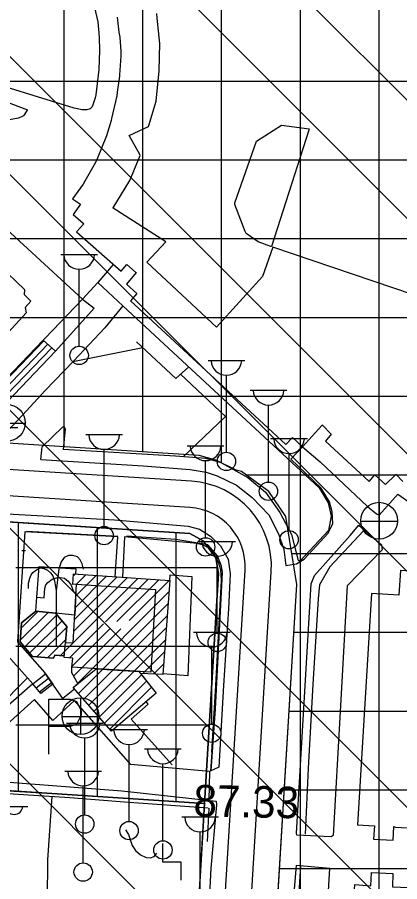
# Model space of a CAD drawing. Extents: x 417995 to 421451, y 4454518 to 4458015.
# Drawn here: x 420586.8 to 420659.6, y 4456253.5 to 4456418.1 of the extents above; entities that cross this region are included whole.
import ezdxf

# ---------------------------------------------------------------- set-up
doc = ezdxf.new("R2010")
doc.units = 0
for name, color, linetype in [('ADAKENARI', 7, 'Continuous'), ('B_Betonzemin', 7, 'Continuous'), ('B_Imalat', 7, 'Continuous'), ('B_Kapi', 7, 'Continuous'), ('B_Merdiven', 7, 'Continuous'), ('B_Resmi', 7, 'Continuous'), ('B_Tarama', 7, 'Continuous'), ('B_Teras', 7, 'Continuous'), ('Hid_Havuz', 7, 'Continuous'), ('KALDIRIM_FAT', 7, 'Continuous'), ('O_Park_Bahce', 7, 'Continuous'), ('PL_KAMU_HİZMET_ALANI', 7, 'Continuous'), ('PL_TİCARET', 7, 'Continuous'), ('S_Cad_Sok_Lambasi', 7, 'Continuous'), ('S_Cesme', 7, 'Continuous'), ('S_Elektrik_Diregi', 7, 'Continuous'), ('S_Otopark', 7, 'Continuous'), ('S_Rogar_Kapagi', 7, 'Continuous'), ('S_Tek_Agac', 7, 'Continuous'), ('Sinir_Duvar_tek_tarafa_ait', 7, 'Continuous'), ('Sinir_Ist_Duvari', 7, 'Continuous'), ('Sinir_Parmaklik_bir_taraf', 7, 'Continuous'), ('Sinir_Tel_bir_taraf', 7, 'Continuous'), ('SN_TR_SIVILASMA', 7, 'Continuous'), ('TRFAT_KHA', 7, 'Continuous'), ('TRFAT_TİCARET', 7, 'Continuous'), ('Y_Yol_Kotu', 7, 'Continuous'), ('Yol_Kaldirim_kenari_bordurtasi', 7, 'Continuous'), ('Yol_Sose', 7, 'Continuous')]:
    doc.layers.add(name, color=color, linetype=linetype)

msp = doc.modelspace()

# ---------------------------------------------------------------- linework, layer by layer
at = {"layer": 'ADAKENARI'}
for p, q in [((420621.4, 4456334.69), (420462.71, 4456344.9)), ((420624.59, 4456333.76), (420621.4, 4456334.69)), ((420628.47, 4456331.87), (420624.59, 4456333.76)), ((420629.47, 4456331.61), (420628.47, 4456331.87)), ((420634.68, 4456327.8), (420629.47, 4456331.61)), ((420637.88, 4456323.02), (420634.68, 4456327.8)), ((420619.6, 4456319.78), (420515.36, 4456326.47)), ((420640, 4456310.1), (420637.88, 4456323.02)), ((420622.14, 4456318.43), (420619.6, 4456319.78)), ((420624.55, 4456315.15), (420622.14, 4456318.43)), ((420625.1, 4456312.17), (420624.55, 4456315.15)), ((420622.45, 4456268.35), (420625.1, 4456312.17)), ((420623.45, 4456037.14), (420640, 4456310.1)), ((420538.18, 4456273.87), (420592.42, 4456270.32)), ((420592.42, 4456270.32), (420622.45, 4456268.35)), ((420618.91, 4456209.8), (420622.45, 4456268.35))]:
    msp.add_line(p, q, dxfattribs=at)
at = {"layer": 'B_Betonzemin'}
for points in [[(420610.68, 4456355.21), (420597.38, 4456352.53)], [(420617.84, 4456350.14), (420626.39, 4456342.11), (420618.35, 4456334.43)]]:
    msp.add_lwpolyline(points, dxfattribs=at)
at = {"layer": 'B_Imalat'}
msp.add_lwpolyline([(420605.8, 4456418.18), (420606.1, 4456415.32), (420606.3, 4456414.36), (420606.52, 4456411.66), (420606.49, 4456410.76), (420606.22, 4456407.17), (420606.21, 4456406.93), (420605.8, 4456403.88), (420605.76, 4456403.16), (420604.74, 4456398.89), (420604.62, 4456398.51), (420603.78, 4456395.54), (420601.98, 4456391.18), (420601.69, 4456390.51), (420599.63, 4456386.95), (420599.32, 4456386.36), (420597.3, 4456383.54), (420598.82, 4456382.57), (420597.4, 4456380.59), (420599.35, 4456378.92), (420599.45, 4456378.83), (420598.06, 4456377.29), (420606.53, 4456369.76), (420607.66, 4456371.06), (420609.29, 4456369.62), (420609.38, 4456369.5), (420607.58, 4456367.32), (420609.54, 4456365.56), (420608.33, 4456364.14), (420637.91, 4456336.78), (420639.15, 4456338.13), (420641.07, 4456336.31), (420644.75, 4456340.39), (420644.81, 4456340.5), (420646.54, 4456338.71), (420645.48, 4456337.39), (420653.75, 4456329.71), (420654.87, 4456330.97), (420656.89, 4456329.14), (420658.8, 4456330.99), (420658.86, 4456331.1), (420660.2, 4456329.74)], dxfattribs=at)
msp.add_lwpolyline([(420580.63, 4456381.48), (420580.52, 4456381.22), (420563.48, 4456362.98), (420563.56, 4456362.98), (420581.88, 4456346.4), (420582.07, 4456346.6), (420599.18, 4456364.48), (420599.18, 4456364.48)], close=True, dxfattribs=at)
at = {"layer": 'B_Kapi'}
for points in [[(420599.18, 4456364.48), (420602.14, 4456367.62)], [(420623.35, 4456274.46), (420623.24, 4456269)]]:
    msp.add_lwpolyline(points, dxfattribs=at)
at = {"layer": 'B_Merdiven'}
for p, q in [((420582, 4456346.3), (420591.84, 4456356.52)), ((420582.76, 4456345.65), (420592.58, 4456355.86)), ((420581.42, 4456342.8), (420593.33, 4456355.2)), ((420589.73, 4456291.18), (420592.14, 4456293.06)), ((420590.37, 4456290.41), (420592.72, 4456292.25)), ((420591.01, 4456289.65), (420593.3, 4456291.43))]:
    msp.add_line(p, q, dxfattribs=at)
for points in [[(420594.08, 4456354.53), (420582.17, 4456342.14), (420569.36, 4456353.39), (420570.68, 4456354.83), (420581.96, 4456344.63), (420582.92, 4456345.52), (420581.88, 4456346.4), (420591.69, 4456356.65)], [(420589.73, 4456291.18), (420592.14, 4456293.06), (420593.54, 4456291.08), (420591.25, 4456289.36)]]:
    msp.add_lwpolyline(points, close=True, dxfattribs=at)
at = {"layer": 'B_Resmi'}
for points in [[(420598.03, 4456310.17), (420597.36, 4456310.1), (420597.49, 4456312.13), (420615.79, 4456310.83), (420614.5, 4456292.96), (420610.24, 4456293.13), (420613.24, 4456289.41), (420604.73, 4456282.16), (420597.4, 4456290.48), (420598.33, 4456291.23), (420597.13, 4456293.29), (420597.15, 4456294.33), (420597.33, 4456296.08), (420595.7, 4456296.2), (420595.73, 4456296.52), (420593.94, 4456296.61), (420593.68, 4456296.07), (420589.64, 4456296.35), (420587.33, 4456299.17), (420587.59, 4456302.8), (420590.3, 4456304.99), (420594.02, 4456304.62), (420596.22, 4456302.12), (420595.94, 4456299.07), (420597.41, 4456298.96)], [(420579.71, 4456302.37), (420589.73, 4456291.18), (420578.05, 4456280.97), (420556.86, 4456282.24)]]:
    msp.add_lwpolyline(points, close=True, dxfattribs=at)
at = {"layer": 'B_Tarama'}
for p, q in [((420595.03, 4456296.55), (420609.74, 4456311.26)), ((420597.47, 4456311.72), (420597.85, 4456312.1)), ((420597.53, 4456301.18), (420607.76, 4456311.4)), ((420597.66, 4456303.42), (420605.78, 4456311.54)), ((420597.78, 4456305.67), (420603.79, 4456311.68)), ((420597.91, 4456307.92), (420601.81, 4456311.82)), ((420598.03, 4456310.17), (420599.83, 4456311.96)), ((420603.58, 4456302.99), (420611.72, 4456311.12)), ((420605.74, 4456303.02), (420613.7, 4456310.98)), ((420608.06, 4456303.22), (420615.68, 4456310.84)), ((420598.28, 4456291.32), (420615.63, 4456308.67)), ((420598.41, 4456289.33), (420615.47, 4456306.39)), ((420587.35, 4456299.48), (420592.63, 4456304.76)), ((420587.52, 4456301.77), (420590.7, 4456304.95)), ((420588.15, 4456298.16), (420594.3, 4456304.31)), ((420589.11, 4456297), (420595.29, 4456303.18)), ((420599.41, 4456288.2), (420615.3, 4456304.1)), ((420590.52, 4456296.29), (420596.2, 4456301.97)), ((420596.72, 4456296.13), (420603.16, 4456302.57)), ((420597.17, 4456294.45), (420604.37, 4456301.66)), ((420597.5, 4456292.66), (420606.52, 4456301.68)), ((420600.4, 4456287.08), (420615.14, 4456301.81)), ((420592.5, 4456296.15), (420596, 4456299.64)), ((420601.39, 4456285.95), (420614.97, 4456299.53)), ((420610.68, 4456293.12), (420614.81, 4456297.24)), ((420612.72, 4456293.03), (420614.65, 4456294.96)), ((420577.44, 4456281.01), (420588.73, 4456292.3)), ((420602.39, 4456284.82), (420610.45, 4456292.88)), ((420603.38, 4456283.69), (420611.39, 4456291.7)), ((420597.42, 4456290.46), (420597.6, 4456290.64)), ((420604.38, 4456282.56), (420612.34, 4456290.53))]:
    msp.add_line(p, q, dxfattribs=at)
at = {"layer": 'B_Teras'}
msp.add_lwpolyline([(420665.95, 4456364.03), (420635.46, 4456374.37), (420633.49, 4456368.74), (420624.73, 4456359.14), (420611.47, 4456371.5), (420615.08, 4456375.4), (420605.01, 4456381.79), (420605.01, 4456381.83), (420608.22, 4456387.04), (420608.22, 4456387.04), (420610.18, 4456391.85), (420610.11, 4456391.98), (420608.09, 4456395.62), (420611.79, 4456397.35), (420611.82, 4456397.56), (420613.23, 4456402.15), (420613.79, 4456407.94), (420613.94, 4456413.17), (420613.43, 4456417.99), (420613.33, 4456418.89)], dxfattribs=at)
for points in [[(420642.35, 4456396.87), (420642.29, 4456396.66), (420635.21, 4456374.47), (420635.04, 4456374.51), (420632.65, 4456375.38), (420630.36, 4456376.97), (420630.18, 4456377.35), (420628.22, 4456382.48), (420628.22, 4456382.8), (420632.32, 4456394.57), (420632.32, 4456394.57), (420637.06, 4456397.59)], [(420583.32, 4456370.88), (420583.32, 4456370.88), (420588.16, 4456366.28), (420588.09, 4456365.35), (420589.37, 4456364.1), (420588.27, 4456362.89), (420588.46, 4456361.84), (420583.75, 4456356.68), (420583.16, 4456357.24), (420581.64, 4456355.62), (420580.35, 4456356.89), (420579.23, 4456356.65), (420574.39, 4456361.79), (420574.45, 4456362.24), (420573.28, 4456363.64), (420574.32, 4456364.7), (420574.17, 4456365.79), (420574.21, 4456365.81), (420578.88, 4456370.67), (420579.77, 4456370.76), (420581.08, 4456371.96), (420582.32, 4456370.82)], [(420598.03, 4456310.17), (420613.1, 4456309.13), (420612.2, 4456293.41), (420597.15, 4456294.33), (420597.33, 4456296.08), (420595.7, 4456296.2), (420595.94, 4456299.07), (420597.41, 4456298.96)], [(420595.94, 4456299.07), (420596.22, 4456302.12), (420594.02, 4456304.62), (420590.3, 4456304.99), (420587.59, 4456302.8), (420587.33, 4456299.17), (420589.64, 4456296.35), (420593.68, 4456296.07), (420593.94, 4456296.61), (420595.73, 4456296.52)], [(420609.91, 4456293.55), (420613.24, 4456289.41), (420604.73, 4456282.16), (420597.4, 4456290.48), (420601.8, 4456294.05)]]:
    msp.add_lwpolyline(points, close=True, dxfattribs=at)
at = {"layer": 'Hid_Havuz'}
for points in [[(420599.4, 4456312.99), (420599.16, 4456314.04), (420598.77, 4456314.81), (420598.21, 4456315.37), (420597.34, 4456315.62), (420596.5, 4456315.62), (420595.69, 4456315.23), (420595.13, 4456314.39), (420594.68, 4456313.06), (420594.15, 4456308.86)], [(420588.9, 4456309.35), (420588.94, 4456310.37), (420589.15, 4456311.31), (420589.43, 4456311.91), (420589.74, 4456312.36), (420590.41, 4456312.92), (420591.11, 4456313.24), (420591.84, 4456313.13), (420592.54, 4456312.82), (420593.1, 4456312.29), (420593.56, 4456311.73), (420593.84, 4456310.82), (420593.98, 4456310.02), (420594.15, 4456308.86), (420594.15, 4456298.36)]]:
    msp.add_lwpolyline(points, dxfattribs=at)
msp.add_lwpolyline([(420590.49, 4456307.69), (420591.87, 4456307.53), (420591.95, 4456308.42), (420592.02, 4456309.42), (420592.23, 4456310.01), (420592.59, 4456310.45), (420593.42, 4456311.09), (420594.26, 4456311.38), (420595.05, 4456311.45), (420595.77, 4456311.29), (420596.45, 4456310.76), (420597.03, 4456309.94), (420597.46, 4456308.68), (420597.95, 4456308.63), (420597.71, 4456304.27), (420594.02, 4456304.62), (420590.3, 4456304.99)], close=True, dxfattribs=at)
at = {"layer": 'KALDIRIM_FAT'}
for p, q in [((420619.92, 4456329.77), (420400.07, 4456343.92)), ((420619.6, 4456324.78), (420399.21, 4456338.96)), ((420613.57, 4456039.35), (420630.15, 4456312.83)), ((420618.56, 4456039.04), (420635.14, 4456312.53))]:
    msp.add_line(p, q, dxfattribs=at)
for radius in [16.29, 11.29]:
    msp.add_arc((420618.88, 4456313.52), radius, 356.5303, 86.3195, dxfattribs=at)
at = {"layer": 'O_Park_Bahce'}
for points in [[(420601.46, 4456420), (420602.08, 4456417.26), (420602.34, 4456414.38), (420602.43, 4456411.82), (420602.3, 4456408.22), (420601.75, 4456403.35), (420601.6, 4456402.82), (420601.03, 4456401.1), (420600.67, 4456400.69), (420599.99, 4456400.49), (420599.13, 4456400.55), (420597.61, 4456400.85), (420585.47, 4456404.58), (420584.56, 4456404.98), (420584.42, 4456405.04), (420574.57, 4456408.13), (420574.21, 4456408.38), (420574.2, 4456409.57), (420574.22, 4456409.7), (420574.15, 4456412.22), (420574, 4456413.58), (420573.93, 4456413.73), (420573.94, 4456414.21), (420574.07, 4456414.55)], [(420580.13, 4456403.74), (420588.69, 4456400.49), (420588.65, 4456400.43), (420587.93, 4456399.4), (420587.84, 4456399.29), (420587.02, 4456398.91), (420579.59, 4456397.6)], [(420599.18, 4456364.48), (420601.4, 4456362.71), (420594.08, 4456354.53)]]:
    msp.add_lwpolyline(points, dxfattribs=at)
at = {"layer": 'PL_KAMU_HİZMET_ALANI'}
msp.add_lwpolyline([(420383.86, 4456251.47), (420387.5, 4456254.04), (420390.9, 4456256.93), (420394.02, 4456260.12), (420396.85, 4456263.57), (420399.35, 4456267.26), (420401.52, 4456271.16), (420403.32, 4456275.23), (420404.75, 4456279.46), (420405.48, 4456281.76), (420405.76, 4456282.54), (420460.36, 4456278.96), (420512.02, 4456275.58), (420538.18, 4456273.87), (420592.42, 4456270.32), (420622.45, 4456268.35), (420618.91, 4456209.8)], dxfattribs=at)
at = {"layer": 'PL_TİCARET'}
msp.add_lwpolyline([(420623.45, 4456037.14), (420640, 4456310.1), (420637.88, 4456323.02), (420634.68, 4456327.8), (420629.47, 4456331.61), (420628.47, 4456331.87), (420624.59, 4456333.76), (420621.4, 4456334.69), (420462.71, 4456344.9), (420462.86, 4456348.74), (420454.39, 4456348.66), (420437.97, 4456349.54), (420422.37, 4456351.96), (420413.66, 4456354.19), (420405.54, 4456357.63), (420398.67, 4456362.62), (420394.62, 4456367.08), (420390.97, 4456372.75), (420388.74, 4456379.85), (420385.69, 4456393.42), (420394.63, 4456520.03)], dxfattribs=at)
msp.add_lwpolyline([(420515.36, 4456326.47), (420619.6, 4456319.78), (420622.14, 4456318.43), (420624.55, 4456315.15), (420625.1, 4456312.17), (420622.45, 4456268.35), (420592.42, 4456270.32), (420538.18, 4456273.87), (420512.02, 4456275.58), (420513.34, 4456295.79)], close=True, dxfattribs=at)
at = {"layer": 'S_Cad_Sok_Lambasi'}
for p, q in [((420595.06, 4456372.98), (420602.06, 4456372.98)), ((420598.56, 4456355.48), (420598.56, 4456370.15)), ((420623.09, 4456352.79), (420630.09, 4456352.79)), ((420626.59, 4456335.29), (420626.59, 4456349.97)), ((420631.1, 4456347.11), (420638.1, 4456347.11)), ((420634.6, 4456329.61), (420634.6, 4456344.28)), ((420579.85, 4456340), (420586.85, 4456340)), ((420599.81, 4456338.65), (420606.81, 4456338.65)), ((420635.02, 4456337.88), (420642.02, 4456337.88)), ((420603.31, 4456321.15), (420603.31, 4456335.82)), ((420619.12, 4456336.51), (420626.12, 4456336.51)), ((420638.52, 4456320.38), (420638.52, 4456335.05)), ((420622.62, 4456319.01), (420622.62, 4456333.69)), ((420621.34, 4456318.31), (420628.34, 4456318.31)), ((420624.84, 4456300.81), (420624.84, 4456315.49)), ((420620.3, 4456301), (420627.3, 4456301)), ((420623.8, 4456283.5), (420623.8, 4456298.18)), ((420596.12, 4456283.71), (420603.12, 4456283.71)), ((420604.55, 4456282.45), (420611.55, 4456282.45)), ((420599.62, 4456266.21), (420599.62, 4456280.88)), ((420608.05, 4456264.95), (420608.05, 4456279.62)), ((420611, 4456278.77), (420618, 4456278.77)), ((420614.5, 4456261.27), (420614.5, 4456275.95)), ((420595.82, 4456274.56), (420602.82, 4456274.56)), ((420599.32, 4456257.06), (420599.32, 4456271.73)), ((420618.08, 4456265.81), (420625.08, 4456265.81)), ((420621.58, 4456248.31), (420621.58, 4456262.98))]:
    msp.add_line(p, q, dxfattribs=at)
for centre in [(420598.56, 4456353.73), (420626.59, 4456333.54), (420634.6, 4456327.86), (420603.31, 4456319.4), (420638.52, 4456318.63), (420622.62, 4456317.26), (420624.84, 4456299.06), (420623.8, 4456281.75), (420599.62, 4456264.46), (420608.05, 4456263.2), (420614.5, 4456259.52), (420599.32, 4456255.31)]:
    msp.add_circle(centre, 1.75, dxfattribs=at)
for centre in [(420598.56, 4456373.08), (420626.59, 4456352.89), (420634.6, 4456347.21), (420603.31, 4456338.75), (420638.52, 4456337.98), (420622.62, 4456336.62), (420624.84, 4456318.42), (420623.8, 4456301.11), (420599.62, 4456283.81), (420608.05, 4456282.55), (420614.5, 4456278.88), (420599.32, 4456274.66), (420621.58, 4456265.91)]:
    msp.add_arc(centre, 2.93, 183.298, 356.9072, dxfattribs=at)
at = {"layer": 'S_Cesme'}
msp.add_lwpolyline([(420614.44, 4456260.74), (420614.44, 4456257.24), (420617.94, 4456257.24), (420617.94, 4456253.74)], dxfattribs=at)
at = {"layer": 'S_Elektrik_Diregi'}
msp.add_line((420583.52, 4456267.81), (420588.77, 4456267.81), dxfattribs=at)
msp.add_arc((420586.18, 4456267.96), 1.66, 184.8384, 355.1464, dxfattribs=at)
at = {"layer": 'S_Otopark'}
for points in [[(420592.75, 4456288.25), (420596.85, 4456288.25)], [(420592.75, 4456277.75), (420592.75, 4456288.25)], [(420596.85, 4456288.25), (420598.07, 4456287.83), (420598.91, 4456286.11), (420598.91, 4456285.2), (420598.07, 4456283.42), (420596.85, 4456283.07)], [(420596.85, 4456283.07), (420592.75, 4456283.07)]]:
    msp.add_lwpolyline(points, dxfattribs=at)
at = {"layer": 'S_Rogar_Kapagi'}
for p, q in [((420581.26, 4456340.83), (420588.26, 4456340.83)), ((420655.72, 4456318.72), (420655.72, 4456325.72)), ((420652.15, 4456322.19), (420659.15, 4456322.19)), ((420598.86, 4456281.5), (420598.86, 4456288.5)), ((420595.29, 4456284.96), (420602.29, 4456284.96))]:
    msp.add_line(p, q, dxfattribs=at)
for centre in [(420584.77, 4456340.89), (420655.67, 4456322.25), (420598.8, 4456285.02)]:
    msp.add_circle(centre, 3.5, dxfattribs=at)
at = {"layer": 'S_Tek_Agac'}
msp.add_line((420587.67, 4456316.57), (420588.37, 4456316.57), dxfattribs=at)
at = {"layer": 'Sinir_Duvar_tek_tarafa_ait'}
for points in [[(420593.37, 4456269.68), (420592.54, 4456257.63)], [(420607.21, 4456268.64), (420596.8, 4456269.46)], [(420623.15, 4456267.5), (420607.21, 4456268.64)]]:
    msp.add_lwpolyline(points, dxfattribs=at)
at = {"layer": 'Sinir_Ist_Duvari'}
for points in [[(420605.05, 4456371.07), (420602.14, 4456367.62), (420606.87, 4456363.18)], [(420606.87, 4456363.18), (420603.43, 4456358.97)], [(420606.87, 4456363.18), (420619.06, 4456351.88), (420644.23, 4456328.52), (420645.95, 4456325.66), (420646.51, 4456323.13), (420646.04, 4456320.4), (420640.67, 4456314.67)], [(420619.42, 4456351.55), (420616.96, 4456349.36), (420609.49, 4456356.32)], [(420625.66, 4456333.27), (420622.67, 4456334.1), (420616.9, 4456334.54), (420595.52, 4456335.84)], [(420652.71, 4456320.35), (420646.27, 4456313.47), (420644.31, 4456310.05), (420644.05, 4456307.35), (420643.03, 4456291.07), (420642.15, 4456275.11)], [(420597.69, 4456290.15), (420595.47, 4456288.37), (420592.01, 4456293.24)], [(420616.24, 4456275.71), (420608.46, 4456284.45), (420611.72, 4456287.27), (420611.32, 4456287.78)], [(420596.8, 4456269.46), (420552.59, 4456272.31), (420511.85, 4456275.79)]]:
    msp.add_lwpolyline(points, dxfattribs=at)
at = {"layer": 'Sinir_Parmaklik_bir_taraf'}
for points in [[(420605.93, 4456319.22), (420588.54, 4456320.2)], [(420623.72, 4456274.57), (420624.54, 4456286.43), (420625.83, 4456312.36), (420625.67, 4456313.56), (420624.92, 4456315.53), (420623.05, 4456317.64), (420616.99, 4456318.64), (420607.56, 4456319.3)], [(420623.26, 4456267.46), (420622.9, 4456261.13)], [(420640.68, 4456256.49), (420638.37, 4456218.15), (420636.61, 4456189.17), (420636.41, 4456186.95), (420634.87, 4456160.12), (420633.57, 4456138.84)]]:
    msp.add_lwpolyline(points, dxfattribs=at)
at = {"layer": 'Sinir_Tel_bir_taraf'}
msp.add_lwpolyline([(420592.54, 4456257.63), (420592.43, 4456242.43), (420592.11, 4456222.17), (420590.61, 4456199.86), (420589.71, 4456183.61), (420588.88, 4456163.55), (420588.29, 4456145.42), (420587.87, 4456130.4), (420537.64, 4456132.44), (420523.08, 4456133.51), (420524.25, 4456158.68), (420525.77, 4456187.88), (420526.03, 4456206.47), (420558.88, 4456203.15)], dxfattribs=at)
at = {"layer": 'SN_TR_SIVILASMA'}
for p, q in [((421274.64, 4455788.69), (420075.79, 4456987.53)), ((421274.41, 4455766.47), (420135.66, 4456905.22)), ((421273.94, 4455722.03), (420248.84, 4456747.14)), ((421273.71, 4455699.81), (420266.8, 4456706.72)), ((421273.25, 4455655.37), (420276.01, 4456652.61)), ((421273.02, 4455633.15), (420276.28, 4456629.89)), ((421272.55, 4455588.71), (420264.03, 4456597.24))]:
    msp.add_line(p, q, dxfattribs=at)
at = {"layer": 'TRFAT_KHA'}
msp.add_line((420589.37, 4456270.38), (420589.37, 4456270.38), dxfattribs=at)
at = {"layer": 'TRFAT_TİCARET'}
for p, q in [((420595.69, 4456336.34), (420595.69, 4456621.35)), ((420610.69, 4456335.38), (420610.69, 4456617.58)), ((420625.69, 4456333.22), (420625.69, 4456605.29)), ((420640.69, 4456031.44), (420640.69, 4456593)), ((420655.69, 4456033.98), (420655.69, 4456580.72)), ((420386.58, 4456405.99), (420735.43, 4456405.99)), ((420386.24, 4456390.99), (420734.4, 4456390.99)), ((420389.95, 4456375.99), (420733.38, 4456375.99)), ((420400.91, 4456360.99), (420732.36, 4456360.99)), ((420462.75, 4456345.99), (420731.34, 4456345.99)), ((420630.32, 4456330.99), (420665.19, 4456330.99)), ((420587.02, 4456270.67), (420587.02, 4456321.87)), ((420602.02, 4456269.69), (420602.02, 4456320.91)), ((420617.02, 4456268.71), (420617.02, 4456319.95)), ((420639.03, 4456315.99), (420665.19, 4456315.99)), ((420586.49, 4456313.35), (420624.88, 4456313.35)), ((420639.45, 4456300.99), (420728.27, 4456300.99)), ((420586.49, 4456298.35), (420624.26, 4456298.35)), ((420638.54, 4456285.99), (420727.25, 4456285.99)), ((420586.49, 4456283.35), (420623.36, 4456283.35)), ((420637.63, 4456270.99), (420726.23, 4456270.99)), ((420636.72, 4456255.99), (420725.21, 4456255.99))]:
    msp.add_line(p, q, dxfattribs=at)
at = {"layer": 'Yol_Kaldirim_kenari_bordurtasi'}
for points in [[(420603.43, 4456358.97), (420597.46, 4456352.61)], [(420580.47, 4456334.69), (420587.78, 4456342.38), (420592.09, 4456347.06), (420597.46, 4456352.61)], [(420591.28, 4456333.93), (420591.53, 4456336.32), (420595.42, 4456340.15), (420595.73, 4456340.14), (420595.86, 4456339.72), (420595.52, 4456335.84)], [(420625.66, 4456333.27), (420630.68, 4456330.49), (420634.06, 4456327.66), (420636.76, 4456323.82), (420638.96, 4456319.65), (420640.23, 4456314.64), (420640.67, 4456314.67)], [(420605.41, 4456311.57), (420605.91, 4456319.19), (420588.2, 4456320.14), (420586.83, 4456299.2), (420592.01, 4456293.24)], [(420623.83, 4456278.17), (420624.57, 4456290.85), (420625.69, 4456310.86), (420625.52, 4456312.86), (420625.1, 4456314.35), (420624.15, 4456316.13), (420623.33, 4456316.99), (420622.19, 4456317.59), (420621.1, 4456317.89), (420607.16, 4456319.18), (420606.8, 4456311.47)], [(420590.49, 4456307.69), (420590.91, 4456313.5), (420597.9, 4456313.05), (420597.84, 4456312.1)], [(420615.79, 4456310.83), (420615.88, 4456311.93), (420620, 4456311.61), (420619.27, 4456292.68), (420614.51, 4456293.09)], [(420623.83, 4456278.17), (420623.56, 4456274.56)], [(420642.15, 4456275.11), (420641.56, 4456262.55)], [(420607.36, 4456263.34), (420607.98, 4456262.47), (420608.24, 4456261.52), (420608.63, 4456260.37), (420609.29, 4456259.44), (420610.25, 4456258.59), (420611.3, 4456258.07), (420612.14, 4456258.03), (420612.81, 4456258.27), (420613.36, 4456258.94)]]:
    msp.add_lwpolyline(points, dxfattribs=at)
at = {"layer": 'Yol_Sose'}
for points in [[(420610.74, 4456332.71), (420619.71, 4456332), (420622.77, 4456331.48), (420624.85, 4456330.77), (420628.5, 4456329.04), (420631.5, 4456326.7), (420634.64, 4456323.34), (420636.52, 4456319.77), (420637.52, 4456316.79), (420637.92, 4456313.72), (420639.97, 4456314.04), (420641.42, 4456314.9), (420645.97, 4456319.9), (420646.86, 4456321.71), (420646.75, 4456323.93), (420646.25, 4456325.84), (420644.66, 4456328.46), (420638.87, 4456333.94), (420641.07, 4456336.31), (420644.44, 4456333.49), (420653.47, 4456324.96), (420655.2, 4456323.53)], [(420655.2, 4456323.53), (420655.66, 4456323.28), (420659.25, 4456327.33), (420661.58, 4456325.64), (420668.9, 4456332.9), (420665.92, 4456335.93)], [(420591.28, 4456333.93), (420610.74, 4456332.71)], [(420474.8, 4456330.76), (420495.18, 4456329.36), (420508.58, 4456328.44), (420552.06, 4456325.59), (420577.98, 4456323.93), (420605.29, 4456322.43), (420619.3, 4456321.21), (420621.5, 4456320.66), (420623.59, 4456319.3), (420625.49, 4456317.43), (420626.92, 4456314.92), (420627.31, 4456312.12), (420626.96, 4456305.45), (420626.01, 4456290.87), (420625.12, 4456275.31), (420623.35, 4456274.46), (420608.39, 4456275.82), (420597.66, 4456287.98), (420593.52, 4456284.2), (420590.08, 4456288.19), (420579.42, 4456278.57)], [(420639.96, 4456262.72), (420641.63, 4456291.84), (420642.75, 4456310.24), (420643.35, 4456311.82), (420650.14, 4456319.45), (420651.83, 4456321.37), (420656.14, 4456317.63), (420656.23, 4456316.71), (420649.56, 4456309.81), (420648.25, 4456285.89), (420646.94, 4456262.27), (420646.57, 4456262.05), (420639.98, 4456262.36)], [(420658.78, 4456263.87), (420662.1, 4456263.67), (420664.92, 4456312.42), (420659.75, 4456312.74), (420659.44, 4456308.08), (420654.2, 4456308.36), (420651.58, 4456264.32), (420654.77, 4456264.12)], [(420515.59, 4456276.9), (420551.53, 4456274.13), (420583.55, 4456272.58), (420606.69, 4456270.78), (420624.65, 4456268.85), (420624.69, 4456268.12), (420623.62, 4456256.06), (420622.53, 4456234.54), (420620.95, 4456208.99), (420620.36, 4456208.83), (420601.57, 4456209.91), (420596.24, 4456209.88), (420595.2, 4456182.47), (420594.18, 4456160.48), (420593.33, 4456137.63), (420592.15, 4456114.6), (420591.14, 4456090.23), (420590.19, 4456065.49), (420611.15, 4456052.8), (420611.49, 4456052.12), (420611.45, 4456050.4), (420611.14, 4456046.51)], [(420654.77, 4456264.12), (420654.6, 4456261.55), (420658.37, 4456261.38), (420658.47, 4456263.97), (420658.78, 4456263.87)], [(420639.98, 4456262.36), (420639.96, 4456262.72)], [(420639.89, 4456256.56), (420638.69, 4456242.25), (420637.55, 4456224.04), (420636.04, 4456199.3), (420634.98, 4456180.02), (420633.45, 4456156.46), (420632.44, 4456138.94)], [(420632.44, 4456138.94), (420638.9, 4456138.39), (420638.99, 4456138.57), (420641.5, 4456178.36), (420643.55, 4456210.86), (420645.32, 4456240.17), (420646.3, 4456255.97), (420639.89, 4456256.56)], [(420654.2, 4456255.21), (420658.28, 4456255.06), (420658.2, 4456252.51), (420661.29, 4456252.35), (420654.25, 4456137.35), (420643.7, 4456138.3), (420651.07, 4456252.92), (420654.12, 4456252.68), (420654.2, 4456255.21)]]:
    msp.add_lwpolyline(points, dxfattribs=at)

# ---------------------------------------------------------------- texts
at = {"layer": 'Y_Yol_Kotu'}
msp.add_text('87.33', height=6, rotation=358.8289, dxfattribs=at).set_placement((420620.29, 4456265.95))

doc.saveas('drawing.dxf')
